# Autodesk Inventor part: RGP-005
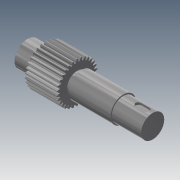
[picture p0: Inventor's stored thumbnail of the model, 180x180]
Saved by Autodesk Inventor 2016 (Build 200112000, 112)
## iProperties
Created: 2013-09
Part Number: RGP-005
Material: Stainless Steel
Document SubType Name: Modeling
Designer: normanpa
Density: 8.08 g/cm^3
Appearance: Semi-Polished
Description: DRIVE GEAR SHAFT
Mass: 2456.46 g
Surface Area: 436.83 cm^2
Volume: 304.018 cm^3
CustomPartVersion: 1
Author: Autodesk
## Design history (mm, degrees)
body "Solid1"
revolve "Revolution1" stored, may be unused: angle "d9" = 0 deg
sketch "Sketch4"
  geometry: A1 r 32 centre (0, 0) between (-3, 31.859) and (3, 31.859) reference; A2 r 27.5 centre (0, 0) between (-1, 27.482) and (1, 27.482); A3 r 32 centre (0, 0) between (-3, 31.859) and (3, 31.859) reference; A4 r 7.5 centre (-8.461, 26.718) between (-1, 27.482) and (-3, 31.859); A5 r 7.5 centre (8.461, 26.718) between (3, 31.859) and (1, 27.482); 1 further point
  constraints: 10 point on circle, 3 centre point, 1 coincident, 1 equal radius
  dimensions: "d14" = 55 diameter of A2; "d15" = 3 horizontal distance of point (0, 0) A1.start; "d16" = 3 horizontal distance of point (0, 0) A1.end (= d15); "d17" = 1 horizontal distance of point (0, 0) A2.start; "d18" = 1 horizontal distance of point (0, 0) A2.end (= d17); "d19" = 7.5 radius of A4
extrude "Extrusion1" cut sketch "Sketch4" stored distance "d20" = 10; taper "d21" = 0 deg
pattern_circular "Circular Pattern1" dims angle "d23" = 360 deg
workplane "Work Plane4"
sketch "Sketch5"
  geometry: L1 (23, -18)-(23, 18) reference; L2 (1, 0)-(13, 0); L3 (1, -5)-(13, -5); L4 (13, 5)-(1, 5); A1 r 5 centre (1, 0) between (1, 5) and (1, -5); A2 r 5 centre (13, 0) between (13, -5) and (13, 5); 3 further points
  constraints: 8 end point, 4 point on circle, 4 tangent, 2 centre point, 2 midpoint, 1 horizontal, 1 horizontal alignment, 1 parallel
  dimensions: "d25" = 12 distance of L2.start L2.end; "d26" = 5 radius of A2; "d27" = 10 distance from line of L2.end L1
extrude "Extrusion2" cut sketch "Sketch5" distance "d28" = 3.5; taper "d29" = 0 deg
node "Origin point"
sketch "Main Sketch"
  geometry: L1 (0, 0)-(196, 0) reference; L2 (0, 0)-(0, 20); L3 (22, 20)-(22, 16); L4 (0, 20)-(22, 20); L5 (22, 16)-(28, 16); L6 (28, 16)-(28, 32); L7 (78, 32)-(78, 16); L8 (28, 32)-(78, 32); L9 (78, 16)-(84, 16); L10 (84, 16)-(84, 20); L11 (150, 20)-(150, 18); L12 (84, 20)-(150, 20); L13 (196, 18)-(196, 0); L14 (150, 18)-(196, 18)
  constraints: 28 end point, 8 horizontal, 7 vertical
  dimensions: "d3" = 40 diameter of L4 L1 (derived); "d4" = 32 diameter of L5 L1 (derived); "d5" = 64 diameter of L8 L1 (derived); "d6" = 32 diameter of L9 L1 (derived); "d7" = 40 diameter of L12 L1 (derived); "d8" = 36 diameter of L14 L1 (derived)
other parameters: "d0" = 0, "d1" = 0, "d2" = 0
